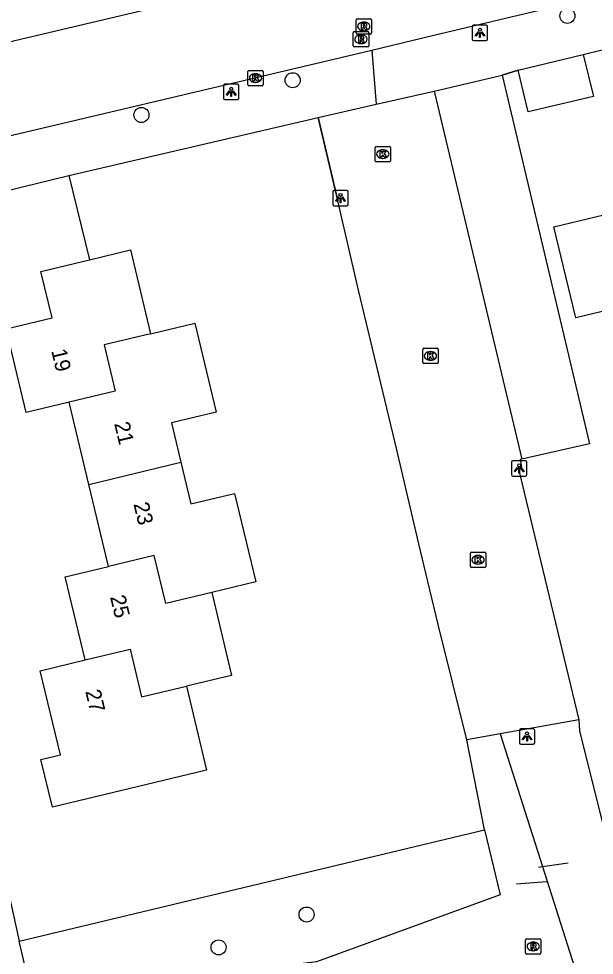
# Model space of a CAD drawing. Extents: x 158038 to 159242, y 380133 to 381214.
# Drawn here: x 158594.2 to 158631.6, y 380444.1 to 380505 of the extents above; entities that cross this region are included whole.
import ezdxf

# ---------------------------------------------------------------- set-up
doc = ezdxf.new("R2010")
doc.units = 0
for name, color, linetype in [('IMGEO_Boom', 7, 'Continuous'), ('IMGEO_Groenvoorziening', 7, 'Continuous'), ('IMGEO_Hek', 7, 'Continuous'), ('IMGEO_Kolk', 7, 'Continuous'), ('IMGEO_Lichtpunt', 7, 'Continuous'), ('IMGEO_Pand', 7, 'Continuous'), ('IMGEO_Pand_nummerreeks', 7, 'Continuous'), ('IMGEO_Parkeervlak_open', 7, 'Continuous'), ('IMGEO_Rijbaan_lokaal_open', 7, 'Continuous'), ('IMGEO_Rioolput', 7, 'Continuous'), ('IMGEO_Voetpad_halfverhard', 7, 'Continuous'), ('IMGEO_Voetpad_open', 7, 'Continuous')]:
    doc.layers.add(name, color=color, linetype=linetype)

msp = doc.modelspace()

# ---------------------------------------------------------------- linework, layer by layer
at = {"layer": 'IMGEO_Boom'}
for centre in [(158629.869, 380505.187), (158612.026, 380501.005), (158602.203, 380498.746), (158612.93, 380446.791), (158607.215, 380444.656)]:
    msp.add_circle(centre, 0.489, dxfattribs=at)
at = {"layer": 'IMGEO_Groenvoorziening'}
for points in [[(158630.604, 380459.446), (158630.649, 380458.734), (158641.564, 380414.924), (158671.368, 380422.189)], [(158594.26, 380445.068), (158624.492, 380452.3)]]:
    msp.add_lwpolyline(points, dxfattribs=at)
at = {"layer": 'IMGEO_Hek'}
for points in [[(158626.674, 380501.666), (158625.623, 380501.336)], [(158625.623, 380501.336), (158631.297, 380477.381), (158626.911, 380476.381)], [(158597.49, 380494.805), (158613.675, 380498.576)], [(158613.675, 380498.576), (158614.95, 380493.157)], [(158616.31, 380487.361), (158614.95, 380493.157)], [(158618.784, 380476.987), (158616.31, 380487.361)], [(158626.911, 380476.381), (158626.804, 380476.357), (158626.881, 380475.872), (158626.673, 380475.831), (158627.993, 380470.342)], [(158628.247, 380449.902), (158629.918, 380450.153)], [(158627.994, 380449.864), (158628.247, 380449.902)], [(158628.524, 380448.914), (158626.558, 380448.759)]]:
    msp.add_lwpolyline(points, dxfattribs=at)
at = {"layer": 'IMGEO_Kolk'}
for p, q in [((158609.187, 380501.646), (158610.039, 380501.646)), ((158609.112, 380500.72), (158609.112, 380501.572)), ((158609.6, 380501.426), (158609.625, 380501.426)), ((158610.113, 380501.572), (158610.113, 380500.72)), ((158610.039, 380500.646), (158609.187, 380500.646)), ((158609.623, 380500.866), (158609.598, 380500.866)), ((158617.382, 380495.777), (158617.382, 380496.629)), ((158617.457, 380496.703), (158618.309, 380496.703)), ((158617.87, 380496.483), (158617.895, 380496.483)), ((158618.383, 380496.629), (158618.383, 380495.777)), ((158618.309, 380495.703), (158617.457, 380495.703)), ((158617.893, 380495.923), (158617.868, 380495.923)), ((158620.477, 380482.662), (158620.477, 380483.514)), ((158620.552, 380483.588), (158621.404, 380483.588)), ((158621.478, 380483.514), (158621.478, 380482.662)), ((158620.988, 380482.808), (158620.963, 380482.808)), ((158620.965, 380483.368), (158620.99, 380483.368)), ((158621.404, 380482.588), (158620.552, 380482.588)), ((158623.566, 380469.416), (158623.566, 380470.268)), ((158623.641, 380470.342), (158624.493, 380470.342)), ((158624.054, 380470.122), (158624.079, 380470.122)), ((158624.567, 380470.268), (158624.567, 380469.416)), ((158624.077, 380469.562), (158624.052, 380469.562)), ((158624.493, 380469.342), (158623.641, 380469.342))]:
    msp.add_line(p, q, dxfattribs=at)
for points in [[(158609.187, 380501.646), (158610.039, 380501.646)], [(158609.112, 380500.72), (158609.112, 380501.572)], [(158609.433, 380501.346), (158609.556, 380501.346), (158609.556, 380501.195), (158609.686, 380501.346), (158609.85, 380501.346), (158609.704, 380501.195), (158609.857, 380500.946), (158609.705, 380500.946), (158609.62, 380501.11), (158609.556, 380501.043), (158609.556, 380500.946), (158609.433, 380500.946), (158609.433, 380501.346)], [(158610.113, 380501.572), (158610.113, 380500.72)], [(158610.039, 380500.646), (158609.187, 380500.646)], [(158617.382, 380495.777), (158617.382, 380496.629)], [(158617.457, 380496.703), (158618.309, 380496.703)], [(158617.703, 380496.403), (158617.826, 380496.403), (158617.826, 380496.252), (158617.956, 380496.403), (158618.12, 380496.403), (158617.974, 380496.252), (158618.127, 380496.003), (158617.975, 380496.003), (158617.89, 380496.167), (158617.826, 380496.1), (158617.826, 380496.003), (158617.703, 380496.003), (158617.703, 380496.403)], [(158618.383, 380496.629), (158618.383, 380495.777)], [(158618.309, 380495.703), (158617.457, 380495.703)], [(158620.477, 380482.662), (158620.477, 380483.514)], [(158620.552, 380483.588), (158621.404, 380483.588)], [(158621.478, 380483.514), (158621.478, 380482.662)], [(158620.798, 380483.288), (158620.921, 380483.288), (158620.921, 380483.137), (158621.051, 380483.288), (158621.215, 380483.288), (158621.069, 380483.137), (158621.222, 380482.888), (158621.07, 380482.888), (158620.985, 380483.052), (158620.921, 380482.985), (158620.921, 380482.888), (158620.798, 380482.888), (158620.798, 380483.288)], [(158621.404, 380482.588), (158620.552, 380482.588)], [(158623.566, 380469.416), (158623.566, 380470.268)], [(158623.641, 380470.342), (158624.493, 380470.342)], [(158623.887, 380470.042), (158624.01, 380470.042), (158624.01, 380469.891), (158624.14, 380470.042), (158624.304, 380470.042), (158624.158, 380469.891), (158624.311, 380469.642), (158624.159, 380469.642), (158624.074, 380469.806), (158624.01, 380469.739), (158624.01, 380469.642), (158623.887, 380469.642), (158623.887, 380470.042)], [(158624.567, 380470.268), (158624.567, 380469.416)], [(158624.493, 380469.342), (158623.641, 380469.342)]]:
    msp.add_lwpolyline(points, dxfattribs=at)
for centre, start, end in [((158609.189, 380501.57), 91.55205, 178.44795), ((158609.189, 380501.57), 91.55205, 178.44795), ((158610.037, 380501.57), 1.55205, 88.44795), ((158610.037, 380501.57), 1.55205, 88.44795), ((158609.189, 380500.722), 181.55205, 268.44795), ((158609.189, 380500.722), 181.55205, 268.44795), ((158610.037, 380500.722), 271.55205, 358.44795), ((158610.037, 380500.722), 271.55205, 358.44795), ((158617.459, 380496.627), 91.55205, 178.44795), ((158617.459, 380496.627), 91.55205, 178.44795), ((158618.307, 380496.627), 1.55205, 88.44795), ((158618.307, 380496.627), 1.55205, 88.44795), ((158617.459, 380495.779), 181.55205, 268.44795), ((158617.459, 380495.779), 181.55205, 268.44795), ((158618.307, 380495.779), 271.55205, 358.44795), ((158618.307, 380495.779), 271.55205, 358.44795), ((158620.554, 380483.512), 91.55205, 178.44795), ((158620.554, 380483.512), 91.55205, 178.44795), ((158621.402, 380483.512), 1.55205, 88.44795), ((158621.402, 380483.512), 1.55205, 88.44795), ((158620.554, 380482.664), 181.55205, 268.44795), ((158620.554, 380482.664), 181.55205, 268.44795), ((158621.402, 380482.664), 271.55205, 358.44795), ((158621.402, 380482.664), 271.55205, 358.44795), ((158623.643, 380470.266), 91.55205, 178.44795), ((158623.643, 380470.266), 91.55205, 178.44795), ((158624.491, 380470.266), 1.55205, 88.44795), ((158624.491, 380470.266), 1.55205, 88.44795), ((158623.643, 380469.418), 181.55205, 268.44795), ((158623.643, 380469.418), 181.55205, 268.44795), ((158624.491, 380469.418), 271.55205, 358.44795), ((158624.491, 380469.418), 271.55205, 358.44795)]:
    msp.add_arc(centre, 0.0765, start, end, dxfattribs=at)
for centre, major_axis, ratio, start_param, end_param in [((158609.599, 380501.146), (-0.387, 0.002), 0.722429, 4.712389, 7.853982), ((158609.624, 380501.146), (-0.39, 0.002), 0.717154, 1.570796, 4.712389), ((158617.869, 380496.203), (-0.387, 0.002), 0.722429, 4.712389, 7.853982), ((158617.894, 380496.203), (-0.39, 0.002), 0.717154, 1.570796, 4.712389), ((158620.964, 380483.088), (-0.387, 0.002), 0.722429, 4.712389, 7.853982), ((158620.989, 380483.088), (-0.39, 0.002), 0.717154, 1.570796, 4.712389), ((158624.053, 380469.842), (-0.387, 0.002), 0.722429, 4.712389, 7.853982), ((158624.078, 380469.842), (-0.39, 0.002), 0.717154, 1.570796, 4.712389)]:
    msp.add_ellipse(centre, major_axis=major_axis, ratio=ratio, start_param=start_param, end_param=end_param, dxfattribs=at)
at = {"layer": 'IMGEO_Lichtpunt'}
for p, q in [((158623.69, 380504.486), (158623.69, 380503.679)), ((158623.69, 380504.486), (158623.69, 380503.679)), ((158624.592, 380504.581), (158623.784, 380504.581)), ((158624.592, 380504.581), (158623.784, 380504.581)), ((158624.686, 380503.679), (158624.686, 380504.486)), ((158624.686, 380503.679), (158624.686, 380504.486)), ((158623.784, 380503.585), (158624.592, 380503.585)), ((158623.784, 380503.585), (158624.592, 380503.585)), ((158607.536, 380500.646), (158607.536, 380499.839)), ((158607.536, 380500.646), (158607.536, 380499.839)), ((158608.438, 380500.741), (158607.63, 380500.741)), ((158608.438, 380500.741), (158607.63, 380500.741)), ((158608.532, 380499.839), (158608.532, 380500.646)), ((158608.532, 380499.839), (158608.532, 380500.646)), ((158607.63, 380499.745), (158608.438, 380499.745)), ((158607.63, 380499.745), (158608.438, 380499.745)), ((158614.633, 380493.754), (158614.633, 380492.947)), ((158614.633, 380493.754), (158614.633, 380492.947)), ((158615.535, 380493.849), (158614.727, 380493.849)), ((158615.535, 380493.849), (158614.727, 380493.849)), ((158615.629, 380492.947), (158615.629, 380493.754)), ((158615.629, 380492.947), (158615.629, 380493.754)), ((158614.727, 380492.853), (158615.535, 380492.853)), ((158614.727, 380492.853), (158615.535, 380492.853)), ((158626.241, 380476.182), (158626.241, 380475.375)), ((158626.241, 380476.182), (158626.241, 380475.375)), ((158627.143, 380476.277), (158626.335, 380476.277)), ((158627.143, 380476.277), (158626.335, 380476.277)), ((158627.237, 380475.375), (158627.237, 380476.182)), ((158627.237, 380475.375), (158627.237, 380476.182)), ((158626.335, 380475.281), (158627.143, 380475.281)), ((158626.335, 380475.281), (158627.143, 380475.281)), ((158626.751, 380458.76), (158626.751, 380457.953)), ((158626.751, 380458.76), (158626.751, 380457.953)), ((158627.653, 380458.855), (158626.845, 380458.855)), ((158627.653, 380458.855), (158626.845, 380458.855)), ((158627.747, 380457.953), (158627.747, 380458.76)), ((158627.747, 380457.953), (158627.747, 380458.76)), ((158626.845, 380457.859), (158627.653, 380457.859)), ((158626.845, 380457.859), (158627.653, 380457.859))]:
    msp.add_line(p, q, dxfattribs=at)
for points in [[(158624.064, 380504.15), (158624.103, 380504.122), (158623.915, 380503.86), (158623.877, 380503.887), (158624.064, 380504.15)], [(158624.166, 380504.102), (158624.213, 380504.102), (158624.213, 380503.78), (158624.166, 380503.78), (158624.166, 380504.102)], [(158624.276, 380504.122), (158624.314, 380504.149), (158624.501, 380503.887), (158624.462, 380503.859), (158624.276, 380504.122)], [(158607.91, 380500.31), (158607.949, 380500.282), (158607.761, 380500.02), (158607.723, 380500.047), (158607.91, 380500.31)], [(158608.012, 380500.262), (158608.059, 380500.262), (158608.059, 380499.94), (158608.012, 380499.94), (158608.012, 380500.262)], [(158608.122, 380500.282), (158608.16, 380500.309), (158608.347, 380500.047), (158608.308, 380500.019), (158608.122, 380500.282)], [(158615.007, 380493.418), (158615.046, 380493.39), (158614.858, 380493.128), (158614.82, 380493.155), (158615.007, 380493.418)], [(158615.109, 380493.37), (158615.156, 380493.37), (158615.156, 380493.048), (158615.109, 380493.048), (158615.109, 380493.37)], [(158615.219, 380493.39), (158615.257, 380493.417), (158615.444, 380493.155), (158615.405, 380493.127), (158615.219, 380493.39)], [(158626.615, 380475.846), (158626.654, 380475.818), (158626.466, 380475.556), (158626.428, 380475.583), (158626.615, 380475.846)], [(158626.717, 380475.798), (158626.764, 380475.798), (158626.764, 380475.476), (158626.717, 380475.476), (158626.717, 380475.798)], [(158626.827, 380475.818), (158626.865, 380475.845), (158627.052, 380475.583), (158627.013, 380475.555), (158626.827, 380475.818)], [(158627.125, 380458.424), (158627.164, 380458.396), (158626.976, 380458.134), (158626.938, 380458.161), (158627.125, 380458.424)], [(158627.227, 380458.376), (158627.274, 380458.376), (158627.274, 380458.054), (158627.227, 380458.054), (158627.227, 380458.376)], [(158627.337, 380458.396), (158627.375, 380458.423), (158627.562, 380458.161), (158627.523, 380458.133), (158627.337, 380458.396)]]:
    msp.add_lwpolyline(points, dxfattribs=at)
for centre in [(158624.189, 380504.284), (158608.035, 380500.444), (158615.132, 380493.552), (158626.74, 380475.98), (158627.25, 380458.558)]:
    msp.add_circle(centre, 0.0994, dxfattribs=at)
for centre, start, end in [((158623.784, 380504.486), 90, 180), ((158623.784, 380504.486), 90, 180), ((158624.592, 380504.486), 0, 90), ((158624.592, 380504.486), 0, 90), ((158623.784, 380503.679), 180, 270), ((158623.784, 380503.679), 180, 270), ((158624.592, 380503.679), 270, 0), ((158624.592, 380503.679), 270, 360), ((158607.63, 380500.646), 90, 180), ((158607.63, 380500.646), 90, 180), ((158608.438, 380500.646), 0, 90), ((158608.438, 380500.646), 0, 90), ((158607.63, 380499.839), 180, 270), ((158607.63, 380499.839), 180, 270), ((158608.438, 380499.839), 270, 0), ((158608.438, 380499.839), 270, 360), ((158614.727, 380493.754), 90, 180), ((158614.727, 380493.754), 90, 180), ((158615.535, 380493.754), 0, 90), ((158615.535, 380493.754), 0, 90), ((158614.727, 380492.947), 180, 270), ((158614.727, 380492.947), 180, 270), ((158615.535, 380492.947), 270, 0), ((158615.535, 380492.947), 270, 360), ((158626.335, 380476.182), 90, 180), ((158626.335, 380476.182), 90, 180), ((158627.143, 380476.182), 0, 90), ((158627.143, 380476.182), 0, 90), ((158626.335, 380475.375), 180, 270), ((158626.335, 380475.375), 180, 270), ((158627.143, 380475.375), 270, 0), ((158627.143, 380475.375), 270, 360), ((158626.845, 380458.76), 90, 180), ((158626.845, 380458.76), 90, 180), ((158627.653, 380458.76), 0, 90), ((158627.653, 380458.76), 0, 90), ((158626.845, 380457.953), 180, 270), ((158626.845, 380457.953), 180, 270), ((158627.653, 380457.953), 270, 0), ((158627.653, 380457.953), 270, 360)]:
    msp.add_arc(centre, 0.0946, start, end, dxfattribs=at)
at = {"layer": 'IMGEO_Pand'}
for points in [[(158626.674, 380501.666), (158630.905, 380502.678)], [(158630.905, 380502.678), (158631.556, 380499.955), (158627.325, 380498.943), (158626.674, 380501.666)], [(158588.105, 380489.392), (158587.386, 380492.338), (158597.49, 380494.805)], [(158597.49, 380494.805), (158598.824, 380489.341)], [(158638.906, 380487.515), (158639.565, 380484.751), (158633.796, 380483.377), (158633.121, 380486.21), (158630.408, 380485.564), (158628.997, 380491.488), (158634.4, 380492.775)], [(158598.824, 380489.341), (158601.483, 380489.979), (158602.789, 380484.534)], [(158593.408, 380484.847), (158596.399, 380485.563), (158595.674, 380488.584), (158598.824, 380489.341)], [(158602.789, 380484.534), (158605.673, 380485.225), (158607.061, 380479.436), (158604.151, 380478.738), (158604.765, 380476.179)], [(158597.503, 380480.078), (158594.712, 380479.408), (158593.408, 380484.847)], [(158602.789, 380484.534), (158599.784, 380483.814), (158600.507, 380480.796), (158597.503, 380480.078)], [(158598.782, 380474.745), (158597.503, 380480.078)], [(158598.782, 380474.745), (158604.765, 380476.179)], [(158604.765, 380476.179), (158605.413, 380473.476), (158608.25, 380474.157), (158609.629, 380468.406), (158606.766, 380467.72)], [(158600.061, 380469.411), (158598.782, 380474.745)], [(158606.766, 380467.72), (158603.785, 380467.006), (158603.036, 380470.129), (158600.061, 380469.411)], [(158598.549, 380463.336), (158597.253, 380468.738), (158600.061, 380469.411)], [(158606.766, 380467.72), (158608.059, 380462.332), (158605.12, 380461.627)], [(158598.549, 380463.336), (158601.461, 380464.036), (158602.206, 380460.928), (158605.12, 380461.627)], [(158605.12, 380461.627), (158606.431, 380456.162), (158596.422, 380453.762), (158595.679, 380456.859), (158596.95, 380457.164), (158595.637, 380462.637), (158598.549, 380463.336)]]:
    msp.add_lwpolyline(points, dxfattribs=at)
at = {"layer": 'IMGEO_Parkeervlak_open'}
msp.add_lwpolyline([(158625.623, 380501.336), (158631.297, 380477.381), (158626.911, 380476.381)], dxfattribs=at)
at = {"layer": 'IMGEO_Rijbaan_lokaal_open'}
for points in [[(158651.329, 380511.074), (158621.203, 380503.911), (158617.159, 380502.945)], [(158580.936, 380500.512), (158623.075, 380510.483)], [(158617.159, 380502.945), (158612.772, 380501.896), (158570.966, 380492.021)], [(158617.449, 380499.44), (158621.222, 380500.303)], [(158621.222, 380500.303), (158626.911, 380476.381)], [(158613.675, 380498.576), (158617.449, 380499.44)], [(158623.328, 380458.135), (158621.477, 380465.634), (158620.797, 380468.423), (158620.226, 380470.871), (158618.784, 380476.987), (158616.31, 380487.361), (158614.95, 380493.157), (158613.675, 380498.576)], [(158626.911, 380476.381), (158626.804, 380476.357), (158626.881, 380475.872), (158626.673, 380475.831), (158627.993, 380470.342), (158630.604, 380459.446)], [(158630.604, 380459.446), (158625.503, 380458.526)], [(158625.503, 380458.526), (158623.328, 380458.135)]]:
    msp.add_lwpolyline(points, dxfattribs=at)
at = {"layer": 'IMGEO_Rioolput'}
for p, q in [((158616.146, 380504.074), (158616.146, 380504.926)), ((158616.221, 380505), (158617.073, 380505)), ((158616.634, 380504.78), (158616.659, 380504.78)), ((158617.147, 380504.926), (158617.147, 380504.074)), ((158615.962, 380503.239), (158615.962, 380504.091)), ((158616.037, 380504.165), (158616.889, 380504.165)), ((158616.657, 380504.22), (158616.632, 380504.22)), ((158616.963, 380504.091), (158616.963, 380503.239)), ((158617.073, 380504), (158616.221, 380504)), ((158616.45, 380503.945), (158616.475, 380503.945)), ((158616.889, 380503.165), (158616.037, 380503.165)), ((158616.473, 380503.385), (158616.448, 380503.385)), ((158627.148, 380444.293), (158627.148, 380445.145)), ((158627.223, 380445.219), (158628.075, 380445.219)), ((158628.149, 380445.145), (158628.149, 380444.293)), ((158627.659, 380444.439), (158627.634, 380444.439)), ((158627.636, 380444.999), (158627.661, 380444.999)), ((158628.075, 380444.219), (158627.223, 380444.219))]:
    msp.add_line(p, q, dxfattribs=at)
for points in [[(158616.146, 380504.074), (158616.146, 380504.926)], [(158616.221, 380505), (158617.073, 380505)], [(158616.735, 380504.698), (158616.483, 380504.7), (158616.483, 380504.3)], [(158617.147, 380504.926), (158617.147, 380504.074)], [(158615.962, 380503.239), (158615.962, 380504.091)], [(158616.037, 380504.165), (158616.889, 380504.165)], [(158616.483, 380504.3), (158616.607, 380504.3), (158616.607, 380504.462), (158616.618, 380504.462)], [(158616.661, 380504.619), (158616.607, 380504.619), (158616.607, 380504.538)], [(158616.607, 380504.538), (158616.659, 380504.538)], [(158616.665, 380504.433), (158616.736, 380504.3), (158616.876, 380504.3), (158616.811, 380504.426)], [(158616.963, 380504.091), (158616.963, 380503.239)], [(158617.073, 380504), (158616.221, 380504)], [(158616.551, 380503.863), (158616.299, 380503.865), (158616.299, 380503.465)], [(158616.299, 380503.465), (158616.423, 380503.465), (158616.423, 380503.627), (158616.434, 380503.627)], [(158616.477, 380503.784), (158616.423, 380503.784), (158616.423, 380503.703)], [(158616.423, 380503.703), (158616.475, 380503.703)], [(158616.481, 380503.598), (158616.552, 380503.465), (158616.692, 380503.465), (158616.627, 380503.591)], [(158616.889, 380503.165), (158616.037, 380503.165)], [(158627.148, 380444.293), (158627.148, 380445.145)], [(158627.223, 380445.219), (158628.075, 380445.219)], [(158628.149, 380445.145), (158628.149, 380444.293)], [(158627.737, 380444.917), (158627.485, 380444.919), (158627.485, 380444.519)], [(158627.485, 380444.519), (158627.609, 380444.519), (158627.609, 380444.681), (158627.62, 380444.681)], [(158627.663, 380444.838), (158627.609, 380444.838), (158627.609, 380444.757)], [(158627.609, 380444.757), (158627.661, 380444.757)], [(158627.667, 380444.652), (158627.738, 380444.519), (158627.878, 380444.519), (158627.813, 380444.645)], [(158628.075, 380444.219), (158627.223, 380444.219)]]:
    msp.add_lwpolyline(points, dxfattribs=at)
for centre, radius, start, end in [((158616.223, 380504.924), 0.0765, 91.55205, 178.44795), ((158616.223, 380504.924), 0.0765, 91.55205, 178.44795), ((158616.734, 380504.588), 0.109, 350.36119, 89.41601), ((158617.071, 380504.924), 0.0765, 1.55205, 88.44795), ((158617.071, 380504.924), 0.0765, 1.55205, 88.44795), ((158616.039, 380504.089), 0.0765, 91.55205, 178.44795), ((158616.039, 380504.089), 0.0765, 91.55205, 178.44795), ((158616.223, 380504.076), 0.0765, 181.55205, 268.44795), ((158616.223, 380504.076), 0.0765, 181.55205, 268.44795), ((158616.617, 380504.409), 0.0533, 26.02933, 88.69889), ((158616.643, 380504.727), 0.19, 274.7715, 282.96867), ((158616.667, 380504.523), 0.0964, 77.00612, 93.18647), ((158616.681, 380504.58), 0.0378, 276.66336, 79.67722), ((158616.732, 380504.588), 0.112, 277.58423, 350.98172), ((158616.716, 380504.373), 0.108, 29.51342, 73.79051), ((158616.887, 380504.089), 0.0765, 1.55205, 88.44795), ((158616.887, 380504.089), 0.0765, 1.55205, 88.44795), ((158617.071, 380504.076), 0.0765, 271.55205, 358.44795), ((158617.071, 380504.076), 0.0765, 271.55205, 358.44795), ((158616.433, 380503.574), 0.0533, 26.02933, 88.69889), ((158616.459, 380503.892), 0.19, 274.7715, 282.96867), ((158616.483, 380503.688), 0.0964, 77.00612, 93.18647), ((158616.497, 380503.745), 0.0378, 276.66336, 79.67722), ((158616.55, 380503.753), 0.109, 350.36119, 89.41601), ((158616.548, 380503.753), 0.112, 277.58423, 350.98172), ((158616.532, 380503.538), 0.108, 29.51342, 73.79051), ((158616.039, 380503.241), 0.0765, 181.55205, 268.44795), ((158616.039, 380503.241), 0.0765, 181.55205, 268.44795), ((158616.887, 380503.241), 0.0765, 271.55205, 358.44795), ((158616.887, 380503.241), 0.0765, 271.55205, 358.44795), ((158627.225, 380445.143), 0.0765, 91.55205, 178.44795), ((158627.225, 380445.143), 0.0765, 91.55205, 178.44795), ((158628.073, 380445.143), 0.0765, 1.55205, 88.44795), ((158628.073, 380445.143), 0.0765, 1.55205, 88.44795), ((158627.619, 380444.628), 0.0533, 26.02933, 88.69889), ((158627.645, 380444.946), 0.19, 274.7715, 282.96867), ((158627.669, 380444.742), 0.0964, 77.00612, 93.18647), ((158627.683, 380444.799), 0.0378, 276.66336, 79.67722), ((158627.736, 380444.807), 0.109, 350.36119, 89.41601), ((158627.734, 380444.807), 0.112, 277.58423, 350.98172), ((158627.718, 380444.592), 0.108, 29.51342, 73.79051), ((158627.225, 380444.295), 0.0765, 181.55205, 268.44795), ((158627.225, 380444.295), 0.0765, 181.55205, 268.44795), ((158628.073, 380444.295), 0.0765, 271.55205, 358.44795), ((158628.073, 380444.295), 0.0765, 271.55205, 358.44795)]:
    msp.add_arc(centre, radius, start, end, dxfattribs=at)
for centre, major_axis, ratio, start_param, end_param in [((158616.633, 380504.5), (-0.387, 0.002), 0.722429, 4.712389, 7.853982), ((158616.658, 380504.5), (-0.39, 0.002), 0.717154, 1.570796, 4.712389), ((158616.449, 380503.665), (-0.387, 0.002), 0.722429, 4.712389, 7.853982), ((158616.474, 380503.665), (-0.39, 0.002), 0.717154, 1.570796, 4.712389), ((158627.635, 380444.719), (-0.387, 0.002), 0.722429, 4.712389, 7.853982), ((158627.66, 380444.719), (-0.39, 0.002), 0.717154, 1.570796, 4.712389)]:
    msp.add_ellipse(centre, major_axis=major_axis, ratio=ratio, start_param=start_param, end_param=end_param, dxfattribs=at)
at = {"layer": 'IMGEO_Voetpad_halfverhard'}
for points in [[(158625.503, 380458.526), (158628.247, 380449.902), (158631.5, 380439.678), (158637.354, 380418.371), (158638.783, 380414.94), (158640.176, 380412.513), (158641.278, 380410.962), (158644.917, 380407.21), (158646.933, 380405.595), (158648.684, 380404.5), (158651.108, 380403.43), (158653.38, 380402.893), (158655.818, 380402.737), (158660.83, 380402.694), (158664.694, 380403.155), (158670.224, 380404.718), (158675.042, 380405.363), (158675.926, 380405.633), (158676.162, 380406.197), (158675.292, 380410.243), (158674.458, 380414.282), (158672.467, 380422.447)], [(158624.492, 380452.3), (158623.328, 380458.135)], [(158624.492, 380452.3), (158625.506, 380448.066), (158613.58, 380443.711), (158602.711, 380442.351), (158599.94, 380442.125), (158594.937, 380442.22), (158594.26, 380445.068)], [(158593.14, 380450.186), (158594.26, 380445.068)]]:
    msp.add_lwpolyline(points, dxfattribs=at)
at = {"layer": 'IMGEO_Voetpad_open'}
for points in [[(158617.159, 380502.945), (158617.449, 380499.44)], [(158630.905, 380502.678), (158632.121, 380502.969)], [(158625.623, 380501.336), (158626.674, 380501.666)], [(158621.222, 380500.303), (158625.623, 380501.336)], [(158597.49, 380494.805), (158613.675, 380498.576)]]:
    msp.add_lwpolyline(points, dxfattribs=at)

# ---------------------------------------------------------------- texts
at = {"layer": 'IMGEO_Pand_nummerreeks'}
for s, rotation, p in [('19', 283.48219, (158596.339, 380483.43)), ('21', 283.48639, (158600.427, 380478.693)), ('23', 283.48395, (158601.679, 380473.469)), ('25', 283.49092, (158600.158, 380467.429)), ('27', 283.49059, (158598.55, 380461.292))]:
    msp.add_text(s, height=1, rotation=rotation, dxfattribs=at).set_placement(p)

doc.saveas('drawing.dxf')
